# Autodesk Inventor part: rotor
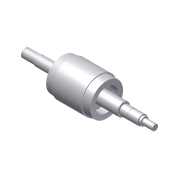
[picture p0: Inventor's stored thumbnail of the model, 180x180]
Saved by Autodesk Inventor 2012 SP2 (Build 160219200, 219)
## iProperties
Created: 2013-04
Part Number: rotor
Material: Default
Document SubType Name: Modeling
Designer: papa
Density: 1 g/cm^3
Mass: 229.803 g
Surface Area: 331.434 cm^2
Volume: 229.803 cm^3
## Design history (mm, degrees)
node "rotor1"
node "rotor"
node "Base1"
